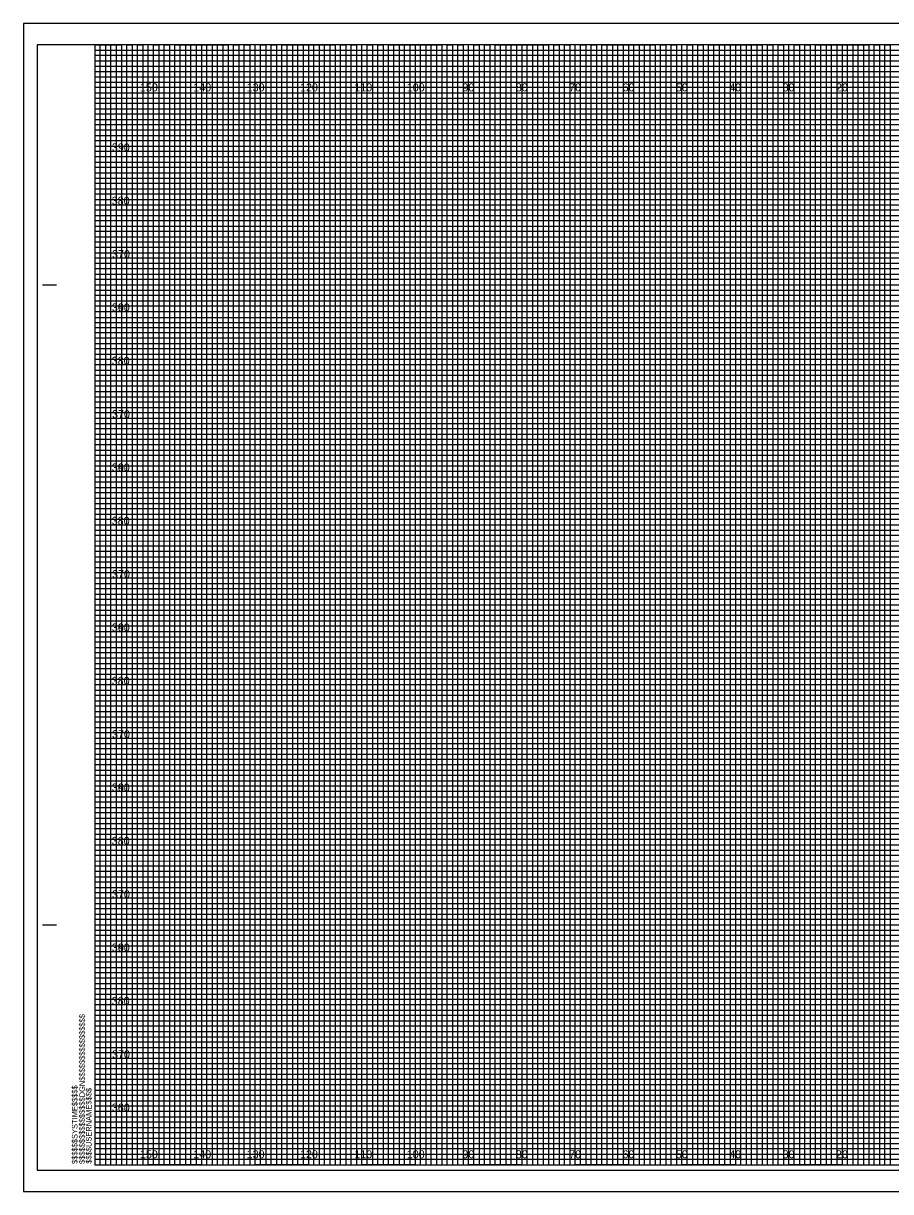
# Model space of a CAD drawing. Extents: x -13 to 323, y 655 to 874.
# Drawn here: x -13.4 to 149.1, y 655 to 874 of the extents above; entities that cross this region are included whole.
import ezdxf

# ---------------------------------------------------------------- set-up
doc = ezdxf.new("R2010")
doc.units = 0
for name, color, linetype in [('Exist Cross Section Cell', 7, 'Continuous'), ('Prop CMT Pvmt Course 1', 7, 'Continuous'), ('Prop CMT Pvmt Course 3', 7, 'Continuous'), ('Prop CMT Shld Paved Course 1', 7, 'Continuous'), ('Prop CMT Shld Paved Course 2', 7, 'Continuous'), ('Prop CMT Shld Paved Course 3', 7, 'Continuous'), ('Prop CMT Slope Grass', 7, 'Continuous'), ('Prop CMT Subgrade Earthwork', 7, 'Continuous'), ('Scratch_Level_3', 7, 'Continuous')]:
    doc.layers.add(name, color=color, linetype=linetype)

msp = doc.modelspace()

# ---------------------------------------------------------------- linework, layer by layer
at = {"layer": 'Prop CMT Pvmt Course 3'}
msp.add_lwpolyline([(-13.4, 655), (323.3, 655), (323.3, 874), (-13.4, 874)], close=True, dxfattribs=at)
at = {"layer": 'Prop CMT Shld Paved Course 1'}
for p, q in [((0, 869), (221.9, 869)), ((221.9, 867.98), (0, 867.98)), ((0, 867.98), (0, 867)), ((0, 867), (221.9, 867)), ((221.9, 865.89), (0, 865.89)), ((0, 865.89), (0, 864)), ((0, 864), (320, 864))]:
    msp.add_line(p, q, dxfattribs=at)
for points in [[(0, 863), (270, 863), (320, 863)], [(320, 862), (0, 862)], [(0, 861), (320, 861)], [(320, 859), (0, 859)], [(0, 858), (320, 858)], [(320, 857), (0, 856.98)], [(0, 856), (320, 856)], [(320, 854), (0, 854)], [(0, 853), (320, 853), (320, 852), (0, 852)], [(0, 851), (320, 851), (320, 849), (0, 849)], [(0, 848), (320, 848), (320, 847), (0, 847)], [(0, 846), (320, 846), (320, 844), (0, 844)], [(0, 843), (320, 843), (320, 842), (0, 842)], [(0, 841), (320, 841), (320, 839), (0, 839)], [(0, 838), (320, 838), (320, 837), (0, 837)], [(0, 836), (320, 836), (320, 833.95), (320, 833), (320, 832), (0, 832)], [(0, 834), (320, 834), (320, 833), (0, 833)], [(0, 831), (320, 831), (320, 829), (0, 829.03)], [(0, 829.03), (320, 829), (320, 828), (0, 828)], [(0, 827), (320, 827), (320, 826), (0, 826)], [(0, 824), (320, 824), (320, 823), (0, 823)], [(0, 822), (320, 822), (320, 821), (0, 821)], [(-0.07, 818.89), (320, 818.89), (320, 817.88), (-0.07, 817.88)], [(0, 817), (320, 817), (320, 816), (0, 816)], [(0, 814), (320, 814), (320, 813), (0, 813)], [(0, 812), (320, 812), (320, 811), (0, 811)], [(0, 809), (320, 809), (320, 808), (0, 808)], [(0, 807), (320, 807), (320, 806), (0, 806)], [(0, 804), (320, 804), (320, 803), (0, 803)], [(0, 802), (320, 802), (320, 801), (0, 801)], [(0, 799), (320, 799), (319.99, 797.98), (0, 798)], [(0, 797), (320, 797), (320, 796), (0, 796)], [(0, 794), (320, 794), (320, 793), (0, 793)], [(0, 792), (320, 792), (320, 791), (0, 791)], [(0, 789), (320, 789), (320, 788), (0, 788)], [(0, 787), (320, 787), (320, 786), (0, 786)], [(0, 784), (320, 784), (320, 783), (0, 783)], [(0, 782), (320, 782), (320, 781), (0, 781)], [(0, 779), (320, 779), (320, 778), (0, 778)], [(0, 776.99), (320.07, 776.91), (320, 776), (0, 776)], [(0, 774), (320, 774), (320, 773), (0, 773)], [(0, 772), (320, 772), (320, 771), (0, 771)], [(0, 769), (320, 769), (320, 768), (0, 768)], [(0, 767), (320, 767), (320, 766), (0, 766)], [(0, 764), (320, 764), (320, 763), (0, 763)], [(0, 762), (320, 762), (320, 761), (0, 761)], [(0, 759), (320, 759), (320, 758), (0, 758)], [(0, 757), (320, 757), (320, 756), (0, 756)], [(0, 754), (320, 754), (320, 753), (0, 753)], [(0, 752), (320, 752), (320, 751), (0, 751)], [(0, 749), (320, 749), (320, 748), (0, 748)], [(0, 747), (320, 747), (320, 746), (0, 746)], [(0, 744), (320, 744), (320, 743), (0, 743)], [(0, 742), (320, 742), (320, 741), (0, 741)], [(0, 739), (320, 739), (319.99, 737.98), (0, 738)], [(0, 737), (320, 737), (320, 736), (0, 736)], [(0, 734), (320, 734), (320, 733), (0, 733)], [(0, 732), (320, 732), (320, 731), (0, 731)], [(0, 729), (320, 729), (320, 728), (0, 728)], [(0, 727), (320, 727), (320, 726), (0, 726)], [(0, 724), (320, 724), (320, 723), (0, 723)], [(0, 722), (320, 722), (320, 721), (0, 721)], [(0, 719), (320, 719), (320, 718), (0, 718)], [(0, 716.99), (320.07, 716.91), (320, 716), (0, 716)], [(0, 714), (320, 714), (320, 713), (0, 713)], [(0, 712), (320, 712), (320, 711), (0, 711)], [(0, 709), (320, 709), (320, 708), (0, 708)], [(0, 707), (320, 707), (320, 706), (0, 706)], [(0, 704), (320, 704), (320, 703), (0, 703)], [(0, 702), (320, 702), (320, 701), (0, 701)], [(0, 699), (320, 699), (320, 698), (0, 698)], [(0, 697), (320, 697), (320, 696), (0, 696)], [(0, 694), (320, 694), (320, 693), (0, 693)], [(0, 692), (320, 692), (320, 691), (0, 691)], [(0, 689), (320, 689), (320, 688), (0, 688)], [(0, 687), (320, 687), (320, 686), (0, 686)], [(0, 684), (320, 684), (320, 683), (0, 683)], [(0, 682), (320, 682), (320, 681), (0, 681)], [(0, 679), (320, 679), (320, 678), (0, 678)], [(0, 677), (320, 677), (320, 676), (0, 676)], [(0, 674), (320, 674), (320, 673), (0, 673)], [(0, 672), (320, 672), (320, 671), (0, 671)], [(0, 669), (320, 669), (320, 668), (0, 668)], [(0, 667), (320, 667), (320, 666), (0, 666)], [(0, 664), (320, 664), (320, 663), (0, 663)], [(0, 662), (320, 662), (320, 661), (0, 661)]]:
    msp.add_lwpolyline(points, dxfattribs=at)
at = {"layer": 'Prop CMT Shld Paved Course 2'}
for p, q in [((-9.8, 825), (-7.3, 825)), ((-9.7, 825), (-7.2, 825)), ((-9.8, 705), (-7.3, 705)), ((-9.7, 705), (-7.2, 705)), ((0, 660), (0, 660)), ((0, 660), (0, 660)), ((0, 660), (0, 660)), ((0, 660), (0, 660)), ((0, 660), (0, 660)), ((0, 660), (0, 660)), ((0, 660), (0, 660))]:
    msp.add_line(p, q, dxfattribs=at)
msp.add_lwpolyline([(320, 870), (0, 870), (0, 660), (320, 660)], close=True, dxfattribs=at)
at = {"layer": 'Prop CMT Shld Paved Course 3'}
for points in [[(0, 660), (1, 660), (1, 870), (2, 870), (2, 660)], [(2, 660), (3, 660), (3, 870), (4, 870), (4, 660)], [(5, 660), (6, 660), (6, 870), (7, 870), (7, 660)], [(7, 660), (8, 660), (8, 870), (9, 870), (9, 660)], [(10, 660), (11, 660), (11, 870), (12, 870), (12, 660)], [(12, 660), (13, 660), (13, 870), (14, 870), (14, 660)], [(15, 660), (16, 660), (16, 870), (17, 870), (17, 660)], [(17, 660), (18, 660), (18, 870), (19, 870), (19, 660)], [(20, 660), (21, 660), (21, 870), (22, 870), (22, 660)], [(22, 660), (23, 660), (23, 870), (24, 870), (24, 660)], [(25, 660), (26, 660), (26, 870), (27, 870), (27, 660)], [(27, 660), (28, 660), (28, 870), (29, 870), (29, 660)], [(30, 660), (31, 660), (31, 870), (32, 870), (32, 660)], [(32, 660), (33, 660), (33, 870), (34, 870), (34, 660)], [(35, 660), (36, 660), (36, 870), (37, 870), (37, 660)], [(37, 660), (38, 660), (38, 870), (39, 870), (39, 660)], [(40, 660), (41, 660), (41, 870), (42, 870), (42, 660)], [(42, 660), (43, 660), (43, 870), (44, 870), (44, 660)], [(45, 660), (46, 660), (46, 870), (47, 870), (47, 660)], [(47, 660), (48, 660), (48, 870), (49, 870), (49, 660)], [(50, 660), (51, 660), (51, 870), (52, 870), (52, 660)], [(52, 660), (53, 660), (53, 870), (54, 870), (54, 660)], [(55, 660), (56, 660), (56, 870), (57, 870), (57, 660)], [(57, 660), (58, 660), (58, 870), (59, 870), (59, 660)], [(60, 660), (61, 660), (61, 870), (62, 870), (62, 660)], [(62, 660), (63, 660), (63, 870), (64, 870), (64, 660)], [(65, 660), (66, 660), (66, 870), (67, 870), (67, 660)], [(67, 660), (68, 660), (68, 870), (69, 870), (69, 660)], [(70, 660), (71, 660), (71, 870), (72, 870), (72, 660)], [(72, 660), (73, 660), (73, 870), (74, 870), (74, 660)], [(75, 660), (76, 660), (76, 870), (77, 870), (77, 660)], [(77, 660), (78, 660), (78, 870), (79, 870), (79, 660)], [(80, 660), (81, 660), (81, 870), (82, 870), (82, 660)], [(82, 660), (83, 660), (83, 870), (84, 870), (84, 660)], [(85, 660), (86, 660), (86, 870), (87, 870), (87, 660)], [(87, 660), (88, 660), (88, 870), (89, 870), (89, 660)], [(90, 660), (91, 660), (91, 870), (92, 870), (92, 660)], [(92, 660), (93, 660), (93, 870), (94, 870), (94, 660)], [(95, 660), (96, 660), (96, 870), (97, 870), (97, 660)], [(97, 660), (98, 660), (98, 870), (99, 870), (99, 660)], [(100, 660), (101, 660), (101, 870), (102, 870), (102, 660)], [(102, 660), (103, 660), (103, 870), (104, 870), (104, 660)], [(105, 660), (106, 660), (106, 870), (107, 870), (107, 660)], [(107, 660), (108, 660), (108, 870), (109, 870), (109, 660)], [(110, 660), (111, 660), (111, 870), (112, 870), (112, 660)], [(112, 660), (113, 660), (113, 870), (114, 870), (114, 660)], [(115, 660), (116, 660), (116, 870), (117, 870), (117, 660)], [(117, 660), (118, 660), (118, 870), (119, 870), (119, 660)], [(120, 660), (121, 660), (121, 870), (122, 870), (122, 660)], [(122, 660), (123, 660), (123, 870), (124, 870), (124, 660)], [(125, 660), (126, 660), (126, 870), (127, 870), (127, 660)], [(127, 660), (128, 660), (128, 870), (129, 870), (129, 660)], [(130, 660), (131, 660), (131, 870), (132, 870), (132, 660)], [(132, 660), (133, 660), (133, 870), (134, 870), (134, 660)], [(135, 660), (136, 660), (136, 870), (137, 870), (137, 660)], [(137, 660), (138, 660), (138, 870), (139, 870), (139, 660)], [(140, 660), (141, 660), (141, 870), (142, 870), (142, 660)], [(142, 660), (143, 660), (143, 870), (144, 870), (144, 660)], [(145, 660), (146, 660), (146, 870), (147, 870), (147, 660)], [(147, 660), (148, 660), (148, 870), (149, 870), (149, 660)]]:
    msp.add_lwpolyline(points, dxfattribs=at)
at = {"layer": 'Prop CMT Slope Grass'}
for points in [[(0, 870), (5, 870), (5, 660), (15, 660), (15, 870), (25, 870), (25, 660), (35, 660), (35, 870), (45, 870), (45, 660), (55, 660), (55, 870), (65, 870), (65, 660), (75, 660), (75, 870), (85, 870), (85, 660), (95, 660), (95, 870), (105, 870), (105, 660), (115, 660), (115, 870), (125, 870), (125, 660), (135, 660), (135, 870), (145, 870), (145, 660), (155, 660)], [(0, 865), (275, 865)], [(0, 845), (320, 845), (320, 865)], [(320, 855), (0, 855)], [(0, 825), (320, 825), (320, 835), (0, 835)], [(0, 805), (320, 805), (320, 815), (0, 815)], [(0, 785), (320, 785), (320, 795), (0, 795)], [(0, 765), (320, 765), (320, 775), (0, 775)], [(0, 745), (320, 745), (320, 755), (0, 755)], [(0, 725), (320, 725), (320, 735), (0, 735)], [(0, 705), (320, 705), (320, 715), (0, 715)], [(0, 685), (320, 685), (320, 695), (0, 695)], [(0, 665), (320, 665), (320, 675), (0, 675)]]:
    msp.add_lwpolyline(points, dxfattribs=at)
at = {"layer": 'Prop CMT Subgrade Earthwork'}
msp.add_lwpolyline([(-10.8, 659), (322.4, 659), (322.4, 870), (-10.8, 870)], close=True, dxfattribs=at)
at = {"layer": 'Scratch_Level_3'}
for p, q in [((10, 870), (0, 870)), ((10, 660), (10, 870)), ((30, 870), (20, 870)), ((20, 870), (20, 660)), ((30, 660), (30, 870)), ((50, 870), (40, 870)), ((40, 870), (40, 660)), ((50, 660), (50, 870)), ((70, 870), (60, 870)), ((60, 870), (60, 660)), ((70, 660), (70, 870)), ((90, 870), (80, 870)), ((80, 870), (80, 660)), ((90, 660), (90, 870)), ((110, 870), (100, 870)), ((100, 870), (100, 660)), ((110, 660), (110, 870)), ((130, 870), (120, 870)), ((120, 870), (120, 660)), ((130, 660), (130, 870)), ((150, 870), (140, 870)), ((140, 870), (140, 660)), ((20, 660), (10, 660)), ((40, 660), (30, 660)), ((60, 660), (50, 660)), ((80, 660), (70, 660)), ((100, 660), (90, 660)), ((120, 660), (110, 660)), ((140, 660), (130, 660))]:
    msp.add_line(p, q, dxfattribs=at)
for points in [[(320, 865), (320, 850), (0, 850)], [(0, 860), (320, 860)], [(0, 840), (320, 840), (320, 830), (0, 830)], [(0, 820), (320, 820), (320, 810), (0, 810)], [(0, 800), (320, 800), (320, 790), (0, 790)], [(0, 780), (320, 780), (320, 770), (0, 770)], [(0, 760), (320, 760), (320, 750), (0, 750)], [(0, 740), (320, 740), (320, 730), (0, 730)], [(0, 720), (320, 720), (320, 710), (0, 710)], [(0, 700), (320, 700), (320, 690), (0, 690)], [(0, 680), (320, 680), (320, 670), (0, 670)]]:
    msp.add_lwpolyline(points, dxfattribs=at)

# ---------------------------------------------------------------- texts
at = {"layer": 'Exist Cross Section Cell'}
for s, p in [('150', (8.44, 861.25)), ('140', (18.44, 861.25)), ('130', (28.44, 861.25)), ('120', (38.44, 861.25)), ('110', (48.62, 861.25)), ('100', (58.44, 861.25)), ('90', (68.86, 861.25)), ('80', (78.86, 861.25)), ('70', (88.86, 861.25)), ('60', (98.86, 861.25)), ('50', (108.86, 861.25)), ('40', (118.86, 861.25)), ('30', (128.86, 861.25)), ('20', (138.86, 861.25)), ('150', (8.44, 661.25)), ('140', (18.44, 661.25)), ('130', (28.44, 661.25)), ('120', (38.44, 661.25)), ('110', (48.62, 661.25)), ('100', (58.44, 661.25)), ('90', (68.86, 661.25)), ('80', (78.86, 661.25)), ('70', (88.86, 661.25)), ('60', (98.86, 661.25)), ('50', (108.86, 661.25)), ('40', (118.86, 661.25)), ('30', (128.86, 661.25)), ('20', (138.86, 661.25))]:
    msp.add_text(s, height=1.5, dxfattribs=at).set_placement(p)
at = {"layer": 'Prop CMT Pvmt Course 1'}
for s, p in [('390', (3.18, 850)), ('380', (3.16, 840)), ('370', (3.22, 830)), ('390', (3.18, 820)), ('360', (3.18, 820)), ('380', (3.16, 810)), ('370', (3.22, 800)), ('390', (3.18, 790)), ('360', (3.18, 790)), ('380', (3.16, 780)), ('370', (3.22, 770)), ('390', (3.18, 760)), ('360', (3.18, 760)), ('380', (3.16, 750)), ('370', (3.22, 740)), ('390', (3.18, 730)), ('360', (3.18, 730)), ('380', (3.16, 720)), ('370', (3.22, 710)), ('390', (3.18, 700)), ('360', (3.18, 700)), ('380', (3.16, 690)), ('370', (3.22, 680)), ('360', (3.18, 670))]:
    msp.add_text(s, height=1.5, dxfattribs=at).set_placement(p)
at = {"layer": 'Prop CMT Shld Paved Course 2'}
for s, p in [('$$$$$$$$$$$$$$$$DGN$$$$$$$$$$$$$$$$', (-1.88, 660.18)), ('$$$$$$SYSTIME$$$$$', (-3.26, 660.18)), ('$$$$USERNAME$$$$', (-0.62, 660.23))]:
    msp.add_text(s, height=1.05, rotation=90, dxfattribs=at).set_placement(p)

doc.saveas('drawing.dxf')
